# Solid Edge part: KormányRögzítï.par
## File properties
Author: morva
Template: iso metric part.par
Last saved by: morva
Revision: 7
Application: Solid Edge
Density: 2712.000 kg/m^3
Accuracy: 0.990
Username: morva
Material: Aluminum, 6061-T6
Face Style: Aluminum
Fill Style: ANSI38(Aluminum)
Virtual Style: Polished aluminum
Grouping: Metals\Aluminium Alloys
LibraryName: Materials
Coef. of Thermal Exp: 2.3e-05
Thermal Conductivity: 180.0
Specific Heat: 920.0
Modulus of Elasticity: 68947570000.0
Poisson's Ratio: 0.33
Yield Stress: 275790280.0
Ultimate Stress: 310264065.0
Elongation: 0.0
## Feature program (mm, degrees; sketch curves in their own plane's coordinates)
sketch for "unnamed Protrusion 1" plane through (0, 0, 0) normal (0, 0, 1) x-axis (1, 0, 0)
  circle centre (0, 0) radius 11
extrude "unnamed Protrusion 1" add finite 51 along +normal
sketch for "ExtrudedProtrusion_2" plane through (0, 0, 51) normal (0, 0, 1) x-axis (1, 0, 0)
  line (-9.798, 5) -> (9.798, 5)
  arc centre (0, 0) radius 11 from (9.798, 5) to (9.798, -5) cw
  line (-9.798, -5) -> (9.798, -5)
extrude "ExtrudedProtrusion_2" add finite 40 along +normal
sketch for "ExtrudedCutout_1" plane through (0, -5, 70) normal (0, -1, 0) x-axis (0, 0, -1)
  circle centre (-6, 0) radius 5
extrude "ExtrudedCutout_1" cut finite 23.6572 along -normal
thread "Thread_2"  ThreadDepth = 50 mm
sketch for "ExtrudedCutout_2" plane through (0, 5, 66) normal (0, 1, 0) x-axis (0, 0, -1)
  line (-20.198, 11) -> (-25.748, 11)
  line (-25.748, -11) -> (-20.198, -11)
extrude "ExtrudedCutout_2" cut finite 14.0956 along -normal
chamfer "Chamfer_1" setback 2
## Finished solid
Body 1: solid body, 10 faces, 17 edges, 8 vertices.
  Faces by surface: plane 5, cylinder 4, cone 1
  Edges by curve: circle 9, line 6, intersection 2
Bounding box of the edges (mm): 22.000 x 22.000 x 91.000, from (-11, -11, 0) to (11, 11, 91).
Cylindrical faces by radius (mm): R5 x1, R11 x2, R15 x1
Conical faces (half-angle, radius in mm at the cone's reference point): 45 deg R9 x1
Planar faces by outward normal: +y 1, +z 2, -y 1, -z 1
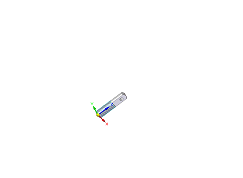
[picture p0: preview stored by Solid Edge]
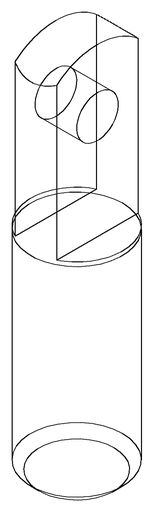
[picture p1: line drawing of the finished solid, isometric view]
